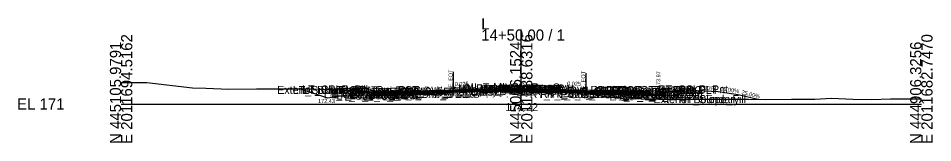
# Model space of a CAD drawing. Extents: x -26 to 4203, y -10 to 9526.
# Drawn here: x -25.7 to 202.8, y 4490.3 to 4521.5 of the extents above; entities that cross this region are included whole.
import ezdxf

# ---------------------------------------------------------------- set-up
doc = ezdxf.new("R2010")
doc.units = 0
for name, color, linetype in [('Default', 7, 'Continuous'), ('Exist CMT Pavement', 7, 'Continuous'), ('Exist Cross Section Cell', 7, 'Continuous'), ('Exist XS Center Line Elevation Label', 7, 'Continuous'), ('Exist XS Ground Line', 7, 'Continuous'), ('Prop CMT Conc Surface', 7, 'Continuous'), ('Prop CMT Concrete Structures', 7, 'Continuous'), ('Prop CMT Pvmt Course 1', 7, 'Continuous'), ('Prop CMT Pvmt Course 1 CG', 7, 'Continuous'), ('Prop CMT Pvmt Course 1 Wedge', 7, 'Continuous'), ('Prop CMT Pvmt Course 2', 7, 'Continuous'), ('Prop CMT Pvmt Course 2 Wedge', 7, 'Continuous'), ('Prop CMT Pvmt Course 3', 7, 'Continuous'), ('Prop CMT Pvmt Course 3 Wedge', 7, 'Continuous'), ('Prop CMT Pvmt Surface', 7, 'Continuous'), ('Prop CMT Pvmt Surface Shoulder', 7, 'Continuous'), ('Prop CMT Pvmt Wedge Surface 1', 7, 'Continuous'), ('Prop CMT Pvmt Wedge Surface 2', 7, 'Continuous'), ('Prop CMT Pvmt Wedge Surface 3', 7, 'Continuous'), ('Prop CMT Shld Paved Course 1', 7, 'Continuous'), ('Prop CMT Shld Paved Course 2', 7, 'Continuous'), ('Prop CMT Shld Paved Course 3', 7, 'Continuous'), ('Prop CMT Slope Grass', 7, 'Continuous'), ('Prop CMT Subgrade Earthwork', 7, 'Continuous'), ('Prop XS Ditch Standard Text', 7, 'Continuous'), ('Prop XS Hydro Elevations', 7, 'Continuous'), ('Prop XS Label Text', 7, 'Continuous'), ('Prop XS SE Text', 7, 'Continuous'), ('Prop XS Side Slope Text', 7, 'Continuous'), ('Scratch_Level_0', 7, 'Continuous')]:
    doc.layers.add(name, color=color, linetype=linetype)

msp = doc.modelspace()

# ---------------------------------------------------------------- linework, layer by layer
at = {"layer": 'Exist CMT Pavement'}
for points in [[(100, 4503.22), (99.45, 4503.22), (98.61, 4503.23), (97.85, 4503.22), (96.08, 4503.22), (95.39, 4503.21), (94.09, 4503.21), (93.73, 4503.21), (91.71, 4503.19), (91.09, 4503.19), (88.78, 4503.17), (88.56, 4503.16), (88.37, 4503.16), (86.08, 4503.11), (85.04, 4503.11), (83.55, 4503.1), (83.54, 4503.1), (82.96, 4503.09), (81.67, 4503.08), (81.56, 4503.08), (81.31, 4503.08), (81.22, 4503.08)], [(100, 4503.22), (101.09, 4503.22), (102.08, 4503.21), (103.57, 4503.19), (104.63, 4503.18), (105.05, 4503.18), (105.42, 4503.17), (106.11, 4503.15), (107.41, 4503.1), (108.6, 4503.05), (110.06, 4503), (111.09, 4502.96), (112.75, 4502.86), (113.61, 4502.81), (114.52, 4502.77), (116.12, 4502.71), (116.15, 4502.7), (116.58, 4502.56), (117.24, 4502.46)]]:
    msp.add_lwpolyline(points, dxfattribs=at)
at = {"layer": 'Exist Cross Section Cell'}
for p, q in [((100, 4500), (100, 4518.65)), ((0, 4500), (100, 4500)), ((100, 4500), (200, 4500))]:
    msp.add_line(p, q, dxfattribs=at)
at = {"layer": 'Exist XS Ground Line'}
msp.add_lwpolyline([(0, 4505.36), (6.42, 4505.41), (17.84, 4504.04), (21.17, 4503.93), (26.95, 4503.73), (33.81, 4503.81), (36.24, 4503.77), (40.93, 4503.78), (47.3, 4503.78), (50.39, 4503.69), (57.32, 4503.45), (59.75, 4503.29), (68.87, 4502.66), (79.71, 4503.03), (81.22, 4503.08), (81.67, 4503.08), (82.96, 4503.09), (83.55, 4503.1), (85.04, 4503.11), (86.08, 4503.11), (88.78, 4503.17), (91.09, 4503.19), (91.71, 4503.19), (93.73, 4503.21), (94.09, 4503.21), (95.39, 4503.21), (96.08, 4503.22), (97.85, 4503.22), (98.61, 4503.23), (99.45, 4503.22), (100, 4503.22), (101.09, 4503.22), (102.08, 4503.21), (103.57, 4503.19), (104.63, 4503.18), (105.05, 4503.18), (105.42, 4503.17), (106.11, 4503.15), (107.41, 4503.1), (108.6, 4503.05), (110.06, 4503), (111.09, 4502.96), (112.75, 4502.86), (113.61, 4502.81), (114.52, 4502.77), (116.12, 4502.71), (116.58, 4502.56), (117.24, 4502.46), (119.1, 4502.23), (121.31, 4501.82), (124.87, 4501.43), (125.54, 4501.4), (134.37, 4501.25), (139.17, 4501.2), (144.26, 4501.21), (151.09, 4501.22), (156.77, 4501.22), (160.94, 4501.14), (167.52, 4501.25), (173.38, 4501.21), (177.54, 4501.5), (182.84, 4501.25), (187.56, 4501.13), (192.3, 4501.26), (197.58, 4501.27), (200, 4501.3)], dxfattribs=at)
at = {"layer": 'Prop CMT Conc Surface'}
msp.add_lwpolyline([(132.25, 4503.1), (134.25, 4502.97)], dxfattribs=at)
at = {"layer": 'Prop CMT Concrete Structures'}
for p, q in [((134.25, 4502.97), (134.75, 4503.08)), ((134.75, 4503.08), (138.75, 4503.24)), ((138.75, 4503.24), (144.25, 4503.35)), ((144.25, 4503.35), (149.25, 4503.15)), ((149.25, 4503.15), (154.25, 4502.4)), ((154.25, 4502.4), (159.14, 4501.18))]:
    msp.add_line(p, q, dxfattribs=at)
for points in [[(107.49, 4503.72), (107.48, 4503.89), (106.73, 4504.14), (99.92, 4504.27), (93.1, 4504.13), (92.35, 4503.88), (92.34, 4503.71)], [(92.34, 4503.71), (100, 4503.91), (107.49, 4503.72)], [(132.25, 4502.52), (132.25, 4503.1)], [(134.75, 4503.08), (134.75, 4502.45), (132.25, 4502.52)]]:
    msp.add_lwpolyline(points, dxfattribs=at)
at = {"layer": 'Prop CMT Pvmt Course 1'}
for points in [[(100, 4503.91), (67.08, 4503.08)], [(67.08, 4502.83), (81.22, 4503.19)], [(67.08, 4503.08), (67.08, 4502.83)], [(82.96, 4503.36), (100, 4503.78)], [(82.96, 4503.23), (82.96, 4503.36)], [(100, 4503.66), (100, 4503.91)], [(100, 4503.91), (132.25, 4503.1)], [(100, 4503.66), (100, 4503.91)], [(100, 4503.78), (100, 4503.66), (100, 4503.66)], [(116.12, 4503.38), (100, 4503.78)], [(100, 4503.78), (100, 4503.66), (100, 4503.66)], [(116.12, 4503.25), (116.12, 4503.38)], [(132.25, 4502.85), (117.24, 4503.23)], [(132.25, 4503.1), (132.25, 4502.85)]]:
    msp.add_lwpolyline(points, dxfattribs=at)
at = {"layer": 'Prop CMT Pvmt Course 1 CG'}
for points in [[(132.25, 4502.52), (135.25, 4502.44), (135.59, 4502.1)], [(132.25, 4502.18), (132.25, 4502.52)], [(135.59, 4502.1), (132.25, 4502.18)]]:
    msp.add_lwpolyline(points, dxfattribs=at)
at = {"layer": 'Prop CMT Pvmt Course 1 Wedge'}
for points in [[(82.96, 4503.36), (82.96, 4503.36), (83.54, 4503.37), (83.55, 4503.37), (85.04, 4503.41), (86.08, 4503.43), (88.37, 4503.49), (88.56, 4503.5), (88.78, 4503.5), (91.09, 4503.56), (91.71, 4503.57), (93.73, 4503.63), (94.09, 4503.63), (95.39, 4503.67), (96.08, 4503.68), (97.85, 4503.73), (98.61, 4503.75), (99.45, 4503.77), (100, 4503.78)], [(100, 4503.66), (99.45, 4503.64), (98.61, 4503.62), (97.85, 4503.6), (96.08, 4503.56), (95.39, 4503.54), (94.09, 4503.51), (93.73, 4503.5), (91.71, 4503.45), (91.09, 4503.43), (88.78, 4503.38), (88.56, 4503.37), (88.37, 4503.37), (86.08, 4503.31), (85.04, 4503.28), (83.55, 4503.25), (83.54, 4503.25), (82.96, 4503.23), (82.96, 4503.23)], [(82.96, 4503.23), (82.96, 4503.36)], [(100, 4503.66), (100, 4503.78)], [(100, 4503.78), (100, 4503.66)], [(100, 4503.78), (101.09, 4503.75), (102.08, 4503.73), (103.57, 4503.69), (104.63, 4503.67), (105.05, 4503.66), (105.42, 4503.65), (106.11, 4503.63), (107.41, 4503.6), (108.6, 4503.57), (110.06, 4503.53), (111.09, 4503.5), (112.75, 4503.46), (113.61, 4503.44), (114.52, 4503.42), (116.12, 4503.38)], [(116.12, 4503.25), (114.52, 4503.29), (113.61, 4503.32), (112.75, 4503.34), (111.09, 4503.38), (110.06, 4503.41), (108.6, 4503.44), (107.41, 4503.47), (106.11, 4503.5), (105.42, 4503.52), (105.05, 4503.53), (104.63, 4503.54), (103.57, 4503.57), (102.08, 4503.6), (101.09, 4503.63), (100, 4503.66)], [(116.12, 4503.38), (116.12, 4503.25)]]:
    msp.add_lwpolyline(points, dxfattribs=at)
at = {"layer": 'Prop CMT Pvmt Course 2'}
for points in [[(82.96, 4503.23), (67.08, 4502.83)], [(67.08, 4502.5), (81.22, 4502.85)], [(67.08, 4502.83), (67.08, 4502.5)], [(82.96, 4502.9), (82.96, 4503.23)], [(116.12, 4502.92), (116.12, 4503.25)], [(116.12, 4503.25), (132.25, 4502.85)], [(132.25, 4502.52), (117.24, 4502.89)], [(132.25, 4502.85), (132.25, 4502.52)]]:
    msp.add_lwpolyline(points, dxfattribs=at)
at = {"layer": 'Prop CMT Pvmt Course 2 Wedge'}
for points in [[(100, 4503.32), (99.45, 4503.31), (98.61, 4503.29), (97.85, 4503.27), (96.08, 4503.23), (95.64, 4503.21), (95.39, 4503.21), (94.09, 4503.21), (93.73, 4503.21), (91.71, 4503.19), (91.09, 4503.19), (88.78, 4503.17), (88.56, 4503.16), (88.37, 4503.16), (86.08, 4503.11), (85.04, 4503.11), (83.55, 4503.1), (83.54, 4503.1), (82.96, 4503.09), (81.67, 4503.08), (81.56, 4503.08), (81.31, 4503.08), (81.22, 4503.08)], [(82.96, 4503.23), (82.96, 4503.23), (83.54, 4503.25), (83.55, 4503.25), (85.04, 4503.28), (86.08, 4503.31), (88.37, 4503.37), (88.56, 4503.37), (88.78, 4503.38), (91.09, 4503.43), (91.71, 4503.45), (93.73, 4503.5), (94.09, 4503.51), (95.39, 4503.54), (96.08, 4503.56), (97.85, 4503.6), (98.61, 4503.62), (99.45, 4503.64), (100, 4503.66)], [(82.96, 4503.13), (82.96, 4503.23)], [(100, 4503.32), (100, 4503.66)], [(100, 4503.66), (100, 4503.32)], [(100, 4503.66), (101.09, 4503.63), (102.08, 4503.6), (103.57, 4503.57), (104.63, 4503.54), (105.05, 4503.53), (105.42, 4503.52), (106.11, 4503.5), (107.41, 4503.47), (108.6, 4503.44), (110.06, 4503.41), (111.09, 4503.38), (112.75, 4503.34), (113.61, 4503.32), (114.52, 4503.29), (116.12, 4503.25)], [(116.12, 4502.92), (114.52, 4502.96), (113.61, 4502.98), (112.75, 4503), (111.09, 4503.05), (110.06, 4503.07), (108.6, 4503.11), (107.41, 4503.14), (106.11, 4503.17), (105.42, 4503.19), (105.05, 4503.2), (104.63, 4503.21), (103.57, 4503.23), (102.08, 4503.27), (101.09, 4503.3), (100, 4503.32)], [(116.12, 4503.25), (116.12, 4502.92)]]:
    msp.add_lwpolyline(points, dxfattribs=at)
at = {"layer": 'Prop CMT Pvmt Course 3'}
for points in [[(82.96, 4502.9), (67.08, 4502.5)], [(67.08, 4502.17), (82.96, 4502.56)], [(67.08, 4502.5), (67.08, 4502.17)], [(82.96, 4502.56), (82.96, 4502.9)], [(116.12, 4502.92), (132.25, 4502.52)], [(116.12, 4502.59), (116.12, 4502.92)], [(132.25, 4502.18), (116.12, 4502.59)], [(132.25, 4502.52), (132.25, 4502.18)]]:
    msp.add_lwpolyline(points, dxfattribs=at)
at = {"layer": 'Prop CMT Pvmt Course 3 Wedge'}
for points in [[(100, 4503.22), (99.45, 4503.22), (98.61, 4503.23), (97.85, 4503.22), (96.08, 4503.22), (95.62, 4503.21)], [(95.62, 4503.21), (96.08, 4503.23)], [(96.08, 4503.23), (97.85, 4503.27), (98.61, 4503.29), (99.45, 4503.31), (100, 4503.32)], [(100, 4503.22), (100, 4503.32)], [(100, 4503.32), (100, 4503.22)], [(100, 4503.32), (101.09, 4503.3), (102.08, 4503.27), (103.57, 4503.23), (104.63, 4503.21), (105.05, 4503.2), (105.42, 4503.19), (106.11, 4503.17), (107.41, 4503.14), (108.6, 4503.11), (110.06, 4503.07), (111.09, 4503.05), (112.75, 4503.01), (113.61, 4502.98), (114.52, 4502.96), (116.12, 4502.92)], [(117.24, 4502.46), (116.58, 4502.56), (116.15, 4502.7), (116.12, 4502.71), (114.52, 4502.77), (113.61, 4502.81), (112.75, 4502.86), (111.09, 4502.96), (110.06, 4503), (108.6, 4503.05), (107.41, 4503.1), (106.11, 4503.15), (105.42, 4503.17), (105.05, 4503.18), (104.63, 4503.18), (103.57, 4503.19), (102.08, 4503.21), (101.09, 4503.22), (100, 4503.22)]]:
    msp.add_lwpolyline(points, dxfattribs=at)
at = {"layer": 'Prop CMT Pvmt Surface'}
for points in [[(100, 4503.91), (67.08, 4503.08)], [(100, 4503.91), (132.25, 4503.1)]]:
    msp.add_lwpolyline(points, dxfattribs=at)
at = {"layer": 'Prop CMT Pvmt Surface Shoulder'}
msp.add_lwpolyline([(67.08, 4503.08), (63.08, 4502.98)], dxfattribs=at)
at = {"layer": 'Prop CMT Pvmt Wedge Surface 1'}
for points in [[(81.22, 4503.19), (67.08, 4502.83)], [(67.08, 4502.83), (67.08, 4503.08)], [(100, 4503.78), (82.96, 4503.36)], [(82.96, 4503.36), (82.96, 4503.23)], [(100, 4503.78), (116.12, 4503.38)], [(116.12, 4503.38), (116.12, 4503.25)], [(117.24, 4503.23), (132.25, 4502.85)], [(132.25, 4502.85), (132.25, 4503.1)]]:
    msp.add_lwpolyline(points, dxfattribs=at)
at = {"layer": 'Prop CMT Pvmt Wedge Surface 2'}
for points in [[(67.08, 4502.83), (67.08, 4503.08)], [(100, 4503.66), (82.96, 4503.23)], [(100, 4503.66), (116.12, 4503.25)], [(132.25, 4502.85), (132.25, 4503.1)]]:
    msp.add_lwpolyline(points, dxfattribs=at)
at = {"layer": 'Prop CMT Pvmt Wedge Surface 3'}
for points in [[(67.08, 4502.5), (67.08, 4503.08)], [(100, 4503.32), (82.96, 4502.9)], [(100, 4503.32), (116.12, 4502.92)], [(132.25, 4502.52), (132.25, 4503.1)]]:
    msp.add_lwpolyline(points, dxfattribs=at)
at = {"layer": 'Prop CMT Shld Paved Course 1'}
for points in [[(67.08, 4503.08), (63.08, 4502.98), (62.82, 4502.73)], [(62.82, 4502.73), (67.08, 4502.83)], [(67.08, 4502.83), (67.08, 4503.08)]]:
    msp.add_lwpolyline(points, dxfattribs=at)
at = {"layer": 'Prop CMT Shld Paved Course 2'}
for points in [[(67.08, 4502.83), (62.82, 4502.73), (62.48, 4502.39)], [(62.48, 4502.39), (67.08, 4502.5)], [(67.08, 4502.5), (67.08, 4502.83)]]:
    msp.add_lwpolyline(points, dxfattribs=at)
at = {"layer": 'Prop CMT Shld Paved Course 3'}
for points in [[(67.08, 4502.5), (62.98, 4502.4), (62.48, 4502.39), (62.14, 4502.04)], [(62.14, 4502.04), (67.08, 4502.17)], [(67.08, 4502.17), (67.08, 4502.5)]]:
    msp.add_lwpolyline(points, dxfattribs=at)
at = {"layer": 'Prop CMT Slope Grass'}
msp.add_lwpolyline([(63.08, 4502.98), (59.08, 4502.66), (51.68, 4501.43), (44.62, 4503.78)], dxfattribs=at)
at = {"layer": 'Prop CMT Subgrade Earthwork'}
for points in [[(67.08, 4502.17), (61.64, 4502.03)], [(82.96, 4502.56), (67.08, 4502.17)], [(82.96, 4502.56), (82.96, 4503.09)], [(116.12, 4502.59), (116.12, 4502.71)], [(116.12, 4502.59), (132.25, 4502.18)], [(132.25, 4502.18), (135.59, 4502.1), (136.64, 4503.16)], [(61.64, 4502.03), (54.16, 4501.84)]]:
    msp.add_lwpolyline(points, dxfattribs=at)
at = {"layer": 'Prop XS Label Text'}
for p, q in [((82.96, 4508.09), (82.96, 4503.09)), ((116.12, 4507.71), (116.12, 4502.71))]:
    msp.add_line(p, q, dxfattribs=at)

# ---------------------------------------------------------------- texts
at = {"layer": 'Default'}
msp.add_text('-', height=0.0001, dxfattribs=at).set_placement((0, 4500))
at = {"layer": 'Exist Cross Section Cell'}
for s, p in [('L', (90, 4518.65)), ('14+50.00 / 1', (90, 4515.85)), ('EL 171', (-26, 4498.6))]:
    msp.add_text(s, height=2.8, dxfattribs=at).set_placement(p)
for s, p in [('E 2011694.5162', (2.8, 4490)), ('E 2011688.6316', (102.8, 4490)), ('E 2011682.7470', (202.8, 4490)), ('N 445105.9791', (0, 4490)), ('N 445006.1524', (100, 4490)), ('N 444906.3256', (200, 4490))]:
    msp.add_text(s, height=2.8, rotation=90, dxfattribs=at).set_placement(p)
at = {"layer": 'Exist XS Center Line Elevation Label'}
msp.add_text('174.22', height=2, dxfattribs=at).set_placement((96.03, 4498.22))
at = {"layer": 'Prop XS Ditch Standard Text'}
msp.add_text('172.43', height=1, dxfattribs=at).set_placement((49.22, 4500.24))
at = {"layer": 'Prop XS Hydro Elevations'}
msp.add_text('173.97', height=1, rotation=90, dxfattribs=at).set_placement((134.75, 4503.97))
at = {"layer": 'Prop XS Label Text'}
for p in [(82.86, 4504.12), (116.02, 4503.73)]:
    msp.add_text('E. EOT', height=1, rotation=90, dxfattribs=at).set_placement(p)
at = {"layer": 'Prop XS SE Text'}
for s, rotation, p in [('0.025', 1.4322, (83.39, 4504.49)), ('0.025', 358.5673, (111.47, 4504.62)), ('4.00%', 2.2906, (134.93, 4503.41)), ('2.00%', 1.1458, (139.69, 4503.45)), ('4.00%', 357.7094, (144.49, 4503.56)), ('15.00%', 351.4692, (149.72, 4503.4)), ('25.00%', 345.9638, (154.99, 4502.5))]:
    msp.add_text(s, height=1, rotation=rotation, dxfattribs=at).set_placement(p)
at = {"layer": 'Prop XS Side Slope Text'}
for s, rotation, p in [('3:1', 341.5676, (46.35, 4503.43)), ('6:1', 9.4617, (52.18, 4502.27))]:
    msp.add_text(s, height=1, rotation=rotation, dxfattribs=at).set_placement(p)
at = {"layer": 'Scratch_Level_0'}
for s, p in [('Exterior Boundary', (39.01, 4502.54)), ('LT_Sub_Trench_Out_DLT', (42.89, 4502.5)), ('LT_CSLP_Pnt', (45.26, 4502.64)), ('LT_Slope_Fill', (45.39, 4502.54)), ('LT_CG_Top_Face', (52.34, 4502.45)), ('LT_CG_Top_BOC', (52.87, 4502.45)), ('MI_Face In', (84.24, 4502.88)), ('MI_Bot In', (85.22, 4502.71)), ('MI_Top In', (85.95, 4503.13)), ('RT_PV2_IEEOP', (89.91, 4502.66)), ('LT_PV2_IEEOP', (89.95, 4502.66)), ('RT_PV1_IEEOP', (90.47, 4502.78)), ('LT_PV1_IEEOP', (90.52, 4502.78)), ('MI_Crown', (92.99, 4503.27)), ('PV2_PGL', (93.91, 4502.66)), ('PV1_PGL', (94.47, 4502.91)), ('MI_Bot', (95.18, 4502.91)), ('MI_Face Out', (97.75, 4502.89)), ('MI_Top Out', (97.96, 4503.14)), ('MI_Bot Out', (98.75, 4502.72)), ('RT_PV1_OEEOP', (107.07, 4502.35)), ('RT_Sub_Trench_Out_DLT', (117.3, 4502.52)), ('RT_CG_Top_Face', (121.24, 4502.48)), ('RT_CG_Top_BOC', (122.76, 4502.48)), ('RT_CSLP_Pnt', (134.15, 4502.67)), ('LT_CG1_Shelf_Out', (50.63, 4501.43)), ('LT_CG_Bot_BOC', (52.9, 4501.44)), ('LT_CG_Top_Gut', (53.32, 4501.95)), ('LT_Sub_OEOP', (53.85, 4501.08)), ('LT_CG_Bot_IE', (57, 4501.5)), ('LT_Sub_OEOT', (57.16, 4501.17)), ('LT_PV2_OEOT', (57.26, 4501.83)), ('LT_PV3_OEOT', (57.26, 4501.5)), ('LT_PV1_OEOT', (57.82, 4502.08)), ('LT_PV_Sub_Tie_Out', (66.18, 4502.08)), ('LT_PV_OEEOP_EG', (68.76, 4502.08)), ('LT_Sub_OEEOP', (70.43, 4501.52)), ('LT_PV2_OEEOP', (70.52, 4502.19)), ('LT_PV3_OEEOP', (70.52, 4501.85)), ('LT_PV1_OEEOP', (71.09, 4502.31)), ('RT_PV_IEEOP_EG', (88.14, 4502.22)), ('LT_PV_IEEOP_EG', (88.19, 4502.22)), ('RT_PV3_IEEOP', (89.91, 4502.32)), ('LT_PV3_IEEOP', (89.95, 4502.32)), ('RT_PV_Sub_Tie_Out', (102.12, 4501.46)), ('RT_PV_OEEOP_EG', (104.74, 4501.46)), ('RT_Sub_OEEOP', (106.4, 4501.56)), ('RT_PV2_OEEOP', (106.5, 4502.23)), ('RT_PV3_OEEOP', (106.5, 4501.89)), ('RT_CG1_Shelf_Out', (121.53, 4501.45)), ('RT_CG_Bot_IE', (121.89, 4501.52)), ('RT_Sub_OEOT', (122.06, 4501.19)), ('RT_PV2_OEOT', (122.15, 4501.86)), ('RT_PV3_OEOT', (122.15, 4501.52)), ('RT_CG_Top_Gut', (122.22, 4501.98)), ('RT_PV1_OEOT', (122.72, 4502.11)), ('RT_CG_Bot_BOC', (122.79, 4501.46)), ('RT_Sub_OEOP', (125.43, 4501.11)), ('Exterior Boundary', (133.07, 4500.22)), ('RT_Slope_Fill', (139.4, 4500.22))]:
    msp.add_text(s, height=2, dxfattribs=at).set_placement(p)

doc.saveas('drawing.dxf')
